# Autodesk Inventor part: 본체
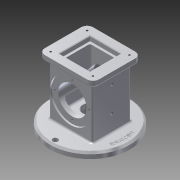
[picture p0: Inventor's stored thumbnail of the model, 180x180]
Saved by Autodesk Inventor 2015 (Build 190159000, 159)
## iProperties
Created: 2019-08
Part Number: 본체
Material: 알루미늄 6061
Document SubType Name: Modeling
Designer: now
Density: 2.7 g/cm^3
Appearance: 알루미늄 - 평지
Mass: 1038.84 g
Surface Area: 783.57 cm^2
Volume: 384.754 cm^3
Author: now
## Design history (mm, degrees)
sketch "스케치1"
  geometry: C1 r 67.5 at (0, 0); 1 further point
  constraints: 1 centre point, 1 coincident
  dimensions: "d0" = 135 diameter of C1
extrude "돌출1" new body sketch "스케치1" distance "d1" = 10; taper "d2" = 0 deg
sketch "스케치2"
  geometry: L1 (-37, -33)-(37, -33); L2 (37, -33)-(37, 33); L3 (37, 33)-(-37, 33); L4 (-37, 33)-(-37, -33); L5 (-37, -33)-(37, 33); L6 (37, -33)-(-37, 33); C1 r 67.5 at (0, 0) reference
  constraints: 12 end point, 2 midpoint, 2 parallel, 1 horizontal, 1 perpendicular
  dimensions: "d3" = 74 distance of L2.end L3.end; "d4" = 66 distance of L1.end L2.end
extrude "돌출2" join sketch "스케치2" distance "d5" = 88; taper "d6" = 0 deg
sketch "스케치3"
  geometry: L1 (-46, -41)-(46, -41); L2 (46, -41)-(46, 41); L3 (46, 41)-(-46, 41); L4 (-46, 41)-(-46, -41); L5 (-46, -41)-(46, 41); L6 (46, -41)-(-46, 41); 1 further point
  constraints: 12 end point, 2 midpoint, 2 parallel, 1 horizontal, 1 perpendicular
  dimensions: "d7" = 92 distance of L2.end L3.end; "d8" = 82 distance of L1.end L2.end
extrude "돌출3" join sketch "스케치3" distance "d9" = 10; taper "d10" = 0 deg
chamfer "모따기1" distance "d11" = 3; stored, may be unused: second distance "d12" = 2, angle "d13" = 45 deg
fillet "모깎기1" dims "d14" = 10
sketch "스케치4"
  geometry: C1 r 67.5 at (0, 0) reference
hole "구멍1" sketch "스케치4" at (0, 0) diameter "d15" = 25; stored, may be unused: countersink angle "d19" = 90 deg, drill point angle "d21" = 0 deg; dims "d16" = 6, "d17" = 50, "d18" = 18, "d20" = 26
sketch "스케치5"
  geometry: L1 (-26, -26)-(26, -26); L2 (26, -26)-(26, 26); L3 (26, 26)-(-26, 26); L4 (-26, 26)-(-26, -26); L5 (-26, -26)-(26, 26); L6 (26, -26)-(-26, 26); 1 further point
  constraints: 12 end point, 2 midpoint, 2 parallel, 1 horizontal, 1 perpendicular
  dimensions: "d22" = 52 distance of L2.end L3.end; "d23" = 52 distance of L1.end L2.end
extrude "돌출4" cut sketch "스케치5" distance "d24" = 8; taper "d25" = 0 deg
sketch "스케치6"
  geometry: L1 (-22, -22)-(22, -22); L2 (22, -22)-(22, 22); L3 (22, 22)-(-22, 22); L4 (-22, 22)-(-22, -22); L5 (-22, -22)-(22, 22); L6 (22, -22)-(-22, 22); 1 further point
  constraints: 12 end point, 2 midpoint, 2 parallel, 1 horizontal, 1 perpendicular
  dimensions: "d26" = 44 distance of L2.end L3.end; "d27" = 44 distance of L3.end L1.start
extrude "돌출5" cut sketch "스케치6" distance "d28" = 74; taper "d29" = 0 deg
fillet "모깎기2" dims "d30" = 3
sketch "스케치8"
  geometry: L1 (-30.5, -10)-(104.5, -10) reference; 3 further points
  constraints: 1 midpoint, 1 vertical alignment
  dimensions: "d39" = 54 distance from line of L1 point (37, 44)
hole "구멍3" sketch "스케치8" at (37, 44) diameter "d40" = 70; stored, may be unused: countersink angle "d44" = 90 deg, drill point angle "d46" = 0 deg; dims "d41" = 6, "d42" = 50, "d43" = 18, "d45" = 3
fillet "모깎기3" dims "d54" = 3
fillet "모깎기4" dims "d55" = 3
sketch "스케치9"
  geometry: C1 r 35 at (0, 0) reference; 1 further point
hole "구멍4" sketch "스케치9" at (0, 0) diameter "d47" = 48; stored, may be unused: countersink angle "d51" = 90 deg, drill point angle "d53" = 0 deg; dims "d48" = 6, "d49" = 50, "d50" = 18, "d52" = 3
sketch "스케치10"
  geometry: C1 r 24 at (0, 0) reference; 2 further points
  constraints: 1 vertical alignment
  dimensions: "d56" = 29 distance of point (0, 29) C1.centre
hole "구멍5" sketch "스케치10" at (0, 29) diameter "d57" = 3.242; stored, may be unused: countersink angle "d61" = 90 deg, drill point angle "d63" = 118 deg; dims "d58" = 4, "d59" = 50, "d60" = 18, "d62" = 6
sketch "스케치11"
  geometry: A1 r 10 centre (36, 31) between (46, 31) and (36, 41) reference; A2 r 10 centre (-36, 31) between (-36, 41) and (-46, 31) reference; A3 r 10 centre (-36, -31) between (-46, -31) and (-36, -41) reference; A4 r 10 centre (36, -31) between (36, -41) and (46, -31) reference; 1 further point
hole "구멍6" sketch "스케치11" at (-36, 31), (36, 31), (-36, -31), (36, -31) diameter "d67" = 3.242; stored, may be unused: countersink angle "d71" = 90 deg, drill point angle "d73" = 118 deg; dims "d68" = 4, "d69" = 50, "d70" = 18, "d72" = 6
sketch "스케치13"
  geometry: C1 r 64.5 at (0, 0) reference; A1 r 59 centre (0, 0) between (0, 59) and (-59, 0)
  constraints: 2 point on circle, 1 centre point, 1 coincident, 1 horizontal alignment, 1 vertical alignment
  dimensions: "d74" = 118 diameter of A1
hole "구멍7" sketch "스케치13" at (0, 59), (-59, 0) diameter "d75" = 9; stored, may be unused: countersink angle "d79" = 90 deg, drill point angle "d81" = 0 deg; dims "d76" = 4, "d77" = 50, "d78" = 18, "d80" = 6
fillet "모깎기5" dims "d82" = 3
fillet "모깎기6" dims "d83" = 3
sketch "스케치14"
  geometry: C1 r 64.5 at (0, 0) reference; C2 r 59 at (0, 0)
  constraints: 1 centre point, 1 coincident, 1 other
  dimensions: "d84" = 118 diameter of C2
feature "엠보싱1" sketch "스케치14" dims "d1" = 10, "d9" = 10, "d85" = 0.5, "d86" = 0
fillet "모깎기7" dims "d87" = 3
sketch "스케치15"
  geometry: L1 (13, -37.5)-(13, 97.5) reference; 4 further points
  constraints: 2 horizontal alignment, 1 midpoint
  dimensions: "d88" = 37 distance from line of point (-24, 30) L1; "d89" = 43 distance of point (-67, 30) point (-24, 30)
hole "구멍8" sketch "스케치15" at (-67, 30), (-24, 30) diameter "d90" = 4.917; stored, may be unused: countersink angle "d94" = 90 deg, drill point angle "d96" = 0 deg; dims "d91" = 12, "d92" = 50, "d93" = 18, "d95" = 30
chamfer "모따기2" distance "d97" = 1; stored, may be unused: second distance "d98" = 2, angle "d99" = 45 deg
node "솔리드1"
mirror "대칭1"
pattern_circular "원형 패턴1" dims angle "d65" = 360 deg
mirror "대칭2"
mirror "대칭3"
